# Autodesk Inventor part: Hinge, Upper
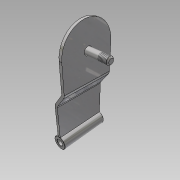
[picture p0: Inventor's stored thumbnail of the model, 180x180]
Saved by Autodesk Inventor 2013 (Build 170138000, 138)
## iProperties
Created: 2012-10
Part Number: Hinge, Upper
Material: Stainless Steel
Document SubType Name: Modeling
Designer: VMuser
Density: 8.08 g/cm^3
Mass: 476.854 g
Surface Area: 298.499 cm^2
Volume: 59.0166 cm^3
Author: VMuser
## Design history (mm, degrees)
derived "Hinge, Upper.iam"
body "Solid1"
node "Hinge 1.ipt:1" dims "d0" = 10
node "List hinge.ipt:1" dims "d0" = 10
node "PK46.51.13.004.ipt:1" dims "d0" = 10
